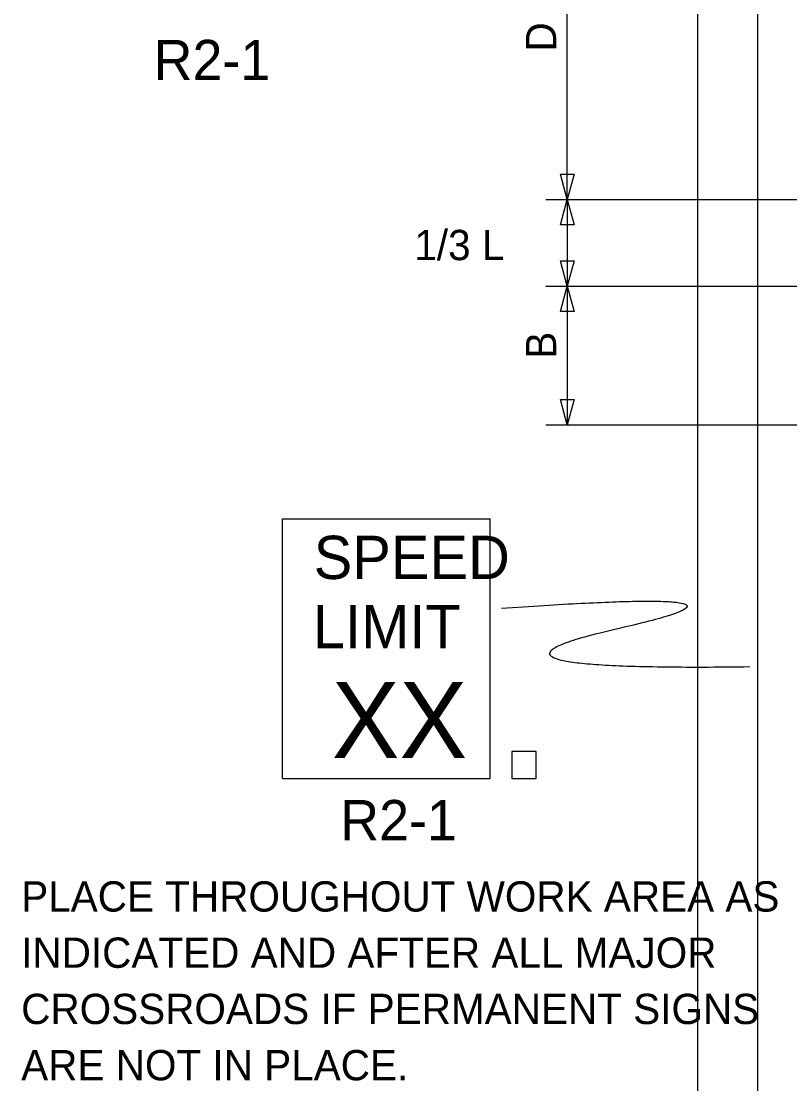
# Model space of a CAD drawing. Extents: x 16743 to 18475, y 7218 to 8262.
# Drawn here: x 16806.9 to 16984.5, y 7726.9 to 7972.5 of the extents above; entities that cross this region are included whole.
import ezdxf

# ---------------------------------------------------------------- set-up
doc = ezdxf.new("R2010")
doc.units = 0
for name, color, linetype in [('PAVT_EDGE_EX', 7, 'Continuous'), ('TRAFFIC_SIGNS_PR', 7, 'Continuous'), ('TYPICAL_TEXT_DIMEN_PR', 7, 'Continuous')]:
    doc.layers.add(name, color=color, linetype=linetype)

msp = doc.modelspace()

# ---------------------------------------------------------------- linework, layer by layer
at = {"layer": 'PAVT_EDGE_EX'}
for p, q in [((16963.15, 8262.34), (16963.15, 7433.15)), ((16977.08, 8216.25), (16977.08, 7378.68))]:
    msp.add_line(p, q, dxfattribs=at)
at = {"layer": 'TRAFFIC_SIGNS_PR'}
for p, q in [((16867.25, 7857.48), (16915.25, 7857.48)), ((16867.25, 7797.48), (16867.25, 7857.48)), ((16915.25, 7797.48), (16915.25, 7857.48)), ((16867.25, 7797.48), (16915.25, 7797.48))]:
    msp.add_line(p, q, dxfattribs=at)
msp.add_lwpolyline([(16920.27, 7797.48), (16925.86, 7797.48), (16925.86, 7803.66), (16920.27, 7803.66)], close=True, dxfattribs=at)
msp.add_open_spline([(16917.89, 7836.8), (16987.12, 7841.69), (16902.1, 7822.34), (16975.26, 7823.3)], degree=2, dxfattribs=at)
at = {"layer": 'TYPICAL_TEXT_DIMEN_PR'}
for p, q in [((16933.08, 7931.25), (16933.08, 8001.25)), ((16933.08, 7931.25), (16931.51, 7937.11)), ((16931.51, 7937.11), (16933.08, 7937.11)), ((16933.08, 7937.11), (16934.65, 7937.11)), ((16934.65, 7937.11), (16933.08, 7931.25)), ((16928.08, 7931.25), (17057.22, 7931.25)), ((16931.51, 7925.39), (16933.08, 7931.25)), ((16933.08, 7931.25), (16933.08, 7911.26)), ((16933.08, 7931.25), (16934.65, 7925.39)), ((16933.08, 7925.39), (16931.51, 7925.39)), ((16934.65, 7925.39), (16933.08, 7925.39)), ((16933.08, 7911.26), (16931.51, 7917.12)), ((16931.51, 7917.12), (16933.08, 7917.12)), ((16933.08, 7917.12), (16934.65, 7917.12)), ((16934.65, 7917.12), (16933.08, 7911.26)), ((16928.08, 7911.26), (17037.78, 7911.26)), ((16931.51, 7905.4), (16933.08, 7911.26)), ((16933.08, 7911.26), (16933.08, 7879.2)), ((16933.08, 7911.26), (16934.65, 7905.4)), ((16933.08, 7905.4), (16931.51, 7905.4)), ((16934.65, 7905.4), (16933.08, 7905.4)), ((16933.08, 7879.2), (16931.51, 7885.06)), ((16931.51, 7885.06), (16933.08, 7885.06)), ((16933.08, 7885.06), (16934.65, 7885.06)), ((16934.65, 7885.06), (16933.08, 7879.2)), ((16928.08, 7879.2), (17037.78, 7879.2))]:
    msp.add_line(p, q, dxfattribs=at)

# ---------------------------------------------------------------- texts
at = {"layer": 'TRAFFIC_SIGNS_PR'}
for s, height, p in [('R2-1', 9.3, (16837.46, 7958.88)), ('SPEED', 10, (16874.46, 7843.56)), ('LIMIT', 10, (16874.26, 7827.56)), ('XX', 17.538, (16878.64, 7802.18)), ('R2-1', 9.3, (16880.6, 7783.18)), ('PLACE THROUGHOUT WORK AREA AS', 7, (16806.84, 7766.69)), ('INDICATED AND AFTER ALL MAJOR', 7, (16806.84, 7753.69)), ('CROSSROADS IF PERMANENT SIGNS', 7, (16806.84, 7740.69)), ('ARE NOT IN PLACE.', 7, (16806.84, 7727.69))]:
    msp.add_text(s, height=height, dxfattribs=at).set_placement(p)
at = {"layer": 'TYPICAL_TEXT_DIMEN_PR'}
for s, p in [('D', (16930.52, 7965.47)), ('B', (16930.52, 7894.47))]:
    msp.add_text(s, height=7, rotation=90, dxfattribs=at).set_placement(p)
msp.add_text('1/3 L', height=7, dxfattribs=at).set_placement((16897.72, 7917.26))

doc.saveas('drawing.dxf')
